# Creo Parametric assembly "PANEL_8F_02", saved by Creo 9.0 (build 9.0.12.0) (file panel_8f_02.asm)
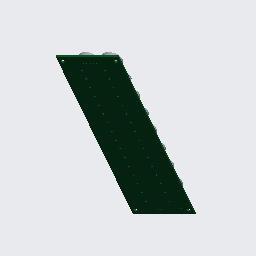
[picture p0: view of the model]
Units: millimeter Newton Second (mmNs); MM, TONNE, SECS

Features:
  1. coordinate system "PANEL_8F_02"
  2. imported feature "Import Feature id 4"
  3. component "PCB_8F"
  4. component "TX_8F_T1"
  5. component "TX_8F_T1"
  6. component "TX_8F_T1"
  7. component "TX_8F_T1"
  8. component "TX_8F_T1"
  9. component "TX_8F_T1"
  10. component "TX_8F_T1"
  11. component "TX_8F_T1"
  12. component "TX_8F_T1"
  13. component "TX_8F_T1"
  14. component "TX_8F_T1"
  15. component "TX_8F_T1"
  16. component "TX_8F_T1"
  17. component "TX_8F_T1"
  18. component "TX_8F_T1"
  19. component "TX_8F_T1"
